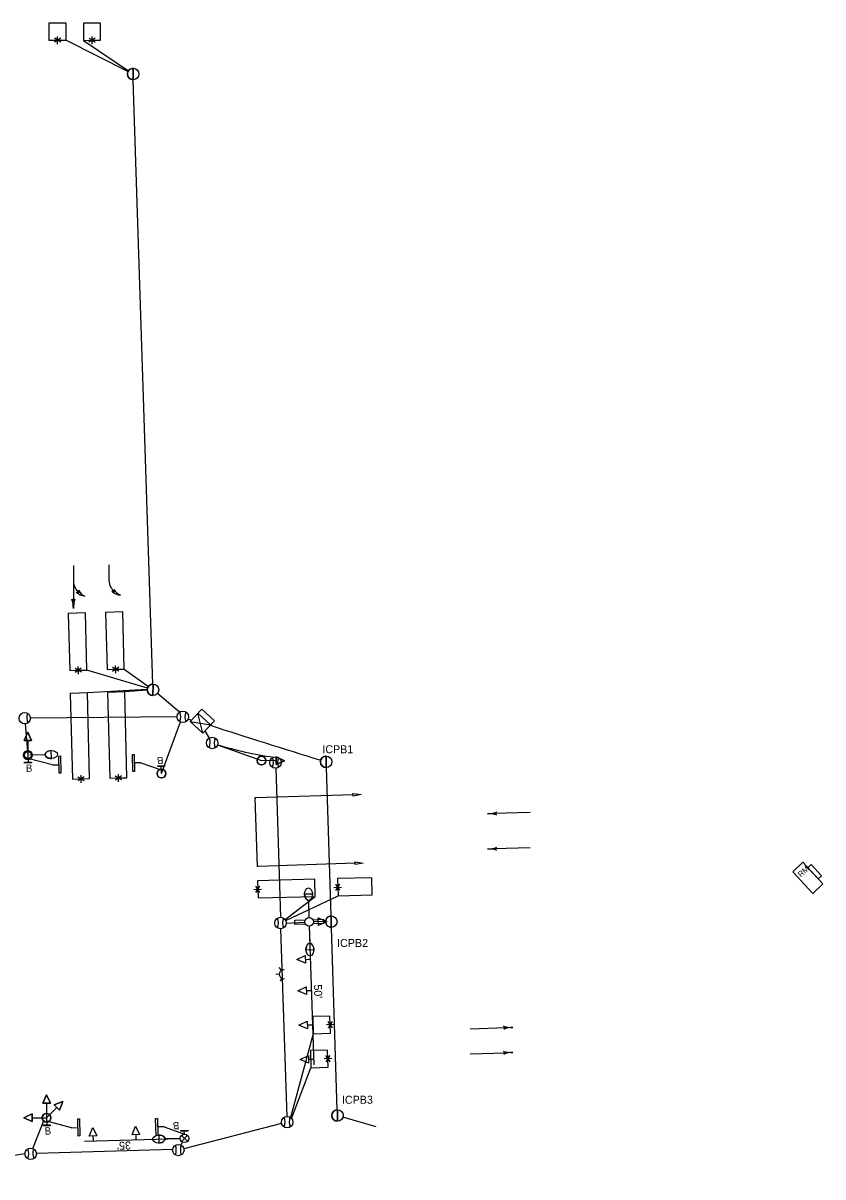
# Model space of a CAD drawing. Extents: x 596176 to 605330, y 332416 to 402398.
# Drawn here: x 604030.9 to 604310.8, y 339271.7 to 339675.2 of the extents above; entities that cross this region are included whole.
import ezdxf

# ---------------------------------------------------------------- set-up
doc = ezdxf.new("R2010")
doc.units = 0
for name, color, linetype in [('P_LTG', 7, 'Continuous'), ('P_SIG', 7, 'Continuous'), ('P_SIG_Bold', 7, 'Continuous'), ('P_SIG_Conduit', 7, 'Continuous'), ('P_SIG_IC', 7, 'Continuous'), ('P_SIG_Loops', 7, 'Continuous'), ('P_SIG_Text', 7, 'Continuous')]:
    doc.layers.add(name, color=color, linetype=linetype)

# ---------------------------------------------------------------- blocks, each defined once
blk = doc.blocks.new('LUMINAIRES')
at = {"layer": 'P_LTG'}
for p, q in [((4.3, 25.1), (-4.1, 25.1)), ((0, 2.3), (0, 18.4))]:
    blk.add_line(p, q, dxfattribs=at)
blk.add_circle((0, 0.1), 3.68, dxfattribs=at)
blk.add_ellipse((0.1, 25.1), major_axis=(0, 6.65), ratio=0.636439, dxfattribs=at)
blk.add_ellipse((0.1, 25.1), major_axis=(0, 6.65), ratio=0.636439, start_param=1.570796, end_param=4.712389, dxfattribs=at)
blk = doc.blocks.new('_U314')
at = {"layer": 'P_LTG'}
for p, q in [((4.3, 25.1), (-4.1, 25.1)), ((0, 2.3), (0, 18.4))]:
    blk.add_line(p, q, dxfattribs=at)
blk.add_ellipse((0.1, 25.1), major_axis=(0, 6.65), ratio=0.636439, dxfattribs=at)
blk.add_ellipse((0.1, 25.1), major_axis=(0, 6.65), ratio=0.636439, start_param=1.570796, end_param=4.712389, dxfattribs=at)
blk = doc.blocks.new('CONTROL CABINET')
at = {"layer": 'P_SIG'}
for p, q in [((-0.229, 0.305), (0.229, 0.305)), ((-0.229, -0.152), (-0.229, 0.305)), ((-0.229, 0.152), (0.229, 0.152)), ((-0.229, -0.152), (0.229, 0.152)), ((0.229, -0.152), (-0.229, 0.152)), ((0.229, 0.305), (0.229, -0.152)), ((0.229, -0.152), (-0.229, -0.152))]:
    blk.add_line(p, q, dxfattribs=at)
blk = doc.blocks.new('_U226')
at = {"layer": 'P_SIG'}
blk.add_line((0, 6.1), (0, -6.1), dxfattribs=at)
blk.add_lwpolyline([(0, -6.1), (0, 6.1)], dxfattribs=at)
blk.add_circle((0, 0), 6.1, dxfattribs=at)
for start, end in [(89.7008, 180), (180, 269.7008)]:
    blk.add_arc((0, 0), 6.1, start, end, dxfattribs=at)

msp = doc.modelspace()

# ---------------------------------------------------------------- linework, layer by layer
at = {"layer": 'P_LTG'}
for p, q in [((604132.2, 339370.57), (604129.43, 339370.51)), ((604130.98, 339362.34), (604130.85, 339368.41)), ((604131.06, 339359.34), (604131.23, 339353.34)), ((604129.9, 339351.11), (604132.67, 339351.19))]:
    msp.add_line(p, q, dxfattribs=at)
for centre, major_axis in [((604130.81, 339370.54), (-0.05, 2.18)), ((604131.28, 339351.15), (0.06, -2.18))]:
    msp.add_ellipse(centre, major_axis=major_axis, ratio=0.636439, dxfattribs=at)
for centre, major_axis in [((604130.81, 339370.54), (-0.05, 2.18)), ((604131.28, 339351.15), (0.06, -2.18))]:
    msp.add_ellipse(centre, major_axis=major_axis, ratio=0.636439, start_param=1.570796, end_param=4.712389, dxfattribs=at)
at = {"layer": 'P_SIG'}
for p, q in [((604069.47, 339659.4), (604069.45, 339655.4)), ((604048.53, 339485.47), (604048.53, 339479.88)), ((604048.53, 339485.47), (604048.53, 339472.9)), ((604060.95, 339485.78), (604060.95, 339480.19)), ((604049.54, 339476.18), (604050.48, 339475.93)), ((604050.3, 339476.83), (604050.48, 339475.93)), ((604061.95, 339476.49), (604062.89, 339476.25)), ((604062.71, 339477.14), (604062.89, 339476.25)), ((604076.38, 339444.01), (604076.36, 339440.01)), ((604089.39, 339430.9), (604093.47, 339435.3)), ((604092.11, 339433.83), (604096.51, 339429.75)), ((604093.79, 339426.82), (604092.11, 339433.83)), ((604093.47, 339435.3), (604097.87, 339431.21)), ((604093.79, 339426.82), (604089.39, 339430.9)), ((604089.39, 339430.9), (604096.51, 339429.75)), ((604097.87, 339431.21), (604093.79, 339426.82)), ((604032.58, 339424.27), (604032.57, 339419.21)), ((604041.2, 339415.78), (604032.53, 339418.02)), ((604032.57, 339419.21), (604032.65, 339416.71)), ((604041.2, 339415.78), (604043.6, 339415.83)), ((604072.09, 339416.52), (604069.69, 339416.47)), ((604072.09, 339416.52), (604079.22, 339413.99)), ((604119.42, 339417.24), (604114.36, 339417.25)), ((604079.31, 339412.71), (604079.23, 339415.21)), ((604208.36, 339399.14), (604195.79, 339398.75)), ((604208.36, 339386.78), (604195.79, 339386.39)), ((604134.26, 339360.94), (604132.49, 339360.89)), ((604129.67, 339347.74), (604131.44, 339347.8)), ((604121.38, 339343.95), (604120.48, 339344.93)), ((604120.56, 339342.52), (604119.33, 339342.5)), ((604121.41, 339341.16), (604120.83, 339340.08)), ((604130.02, 339336.8), (604131.79, 339336.85)), ((604130.4, 339324.8), (604132.17, 339324.86)), ((604187.29, 339323.49), (604199.85, 339323.88)), ((604187.29, 339314.71), (604199.85, 339315.1)), ((604130.77, 339312.81), (604132.54, 339312.86)), ((604039.16, 339297.42), (604039.15, 339292.36)), ((604042.7, 339295.96), (604039.15, 339292.36)), ((604034.09, 339292.37), (604039.15, 339292.36)), ((604039.15, 339292.36), (604039.23, 339289.86)), ((604047.85, 339288.86), (604039.19, 339291.11)), ((604047.85, 339288.86), (604050.25, 339288.92)), ((604070.36, 339286.41), (604070.41, 339284.64)), ((604080.23, 339289.18), (604077.83, 339289.13)), ((604080.23, 339289.18), (604087.36, 339286.64)), ((604087.36, 339286.64), (604087.33, 339287.65)), ((604055.36, 339285.97), (604055.42, 339284.2))]:
    msp.add_line(p, q, dxfattribs=at)
for points in [[(604069.45, 339655.4), (604069.47, 339659.4)], [(604048.03, 339473.7), (604048.53, 339472.9), (604049.03, 339473.7)], [(604076.36, 339440.01), (604076.38, 339444.01)], [(604032.58, 339427.23), (604033.9, 339424.27), (604031.26, 339424.27), (604032.58, 339427.23)], [(604033.9, 339424.27), (604032.58, 339427.23), (604031.26, 339424.27), (604033.9, 339424.27)], [(604122.38, 339417.24), (604119.42, 339415.92), (604119.42, 339418.56), (604122.38, 339417.24)], [(604119.42, 339415.92), (604122.38, 339417.24), (604119.42, 339418.56), (604119.42, 339415.92)], [(604196.58, 339399.28), (604195.79, 339398.75), (604196.61, 339398.28)], [(604196.58, 339386.92), (604195.79, 339386.39), (604196.61, 339385.92)], [(604199.07, 339323.36), (604199.85, 339323.88), (604199.04, 339324.36)], [(604199.07, 339314.58), (604199.85, 339315.1), (604199.04, 339315.58)], [(604039.16, 339300.38), (604040.48, 339297.42), (604037.84, 339297.42), (604039.16, 339300.38)], [(604040.48, 339297.42), (604039.16, 339300.38), (604037.84, 339297.42), (604040.48, 339297.42)], [(604044.78, 339298.07), (604043.64, 339295.04), (604041.76, 339296.88), (604044.78, 339298.07)], [(604043.64, 339295.04), (604044.78, 339298.07), (604041.76, 339296.88), (604043.64, 339295.04)], [(604031.13, 339292.37), (604034.09, 339293.69), (604034.09, 339291.05), (604031.13, 339292.37)], [(604034.09, 339293.69), (604031.13, 339292.37), (604034.09, 339291.05), (604034.09, 339293.69)]]:
    msp.add_lwpolyline(points, dxfattribs=at)
for points in [[(604031.45, 339416.68), (604033.85, 339416.75), (604033.86, 339416.43), (604031.46, 339416.35)], [(604043.53, 339412.87), (604043.39, 339418.87), (604043.99, 339418.88), (604044.13, 339412.88)], [(604069.76, 339419.43), (604069.89, 339413.43), (604069.29, 339413.42), (604069.16, 339419.42)], [(604080.43, 339415.24), (604078.03, 339415.17), (604078.02, 339415.49), (604080.42, 339415.57)], [(604310.76, 339374.11), (604303.72, 339381.69), (604300.18, 339378.41), (604307.23, 339370.83)], [(604306.7, 339380.88), (604305.53, 339379.79), (604309.12, 339375.93), (604310.29, 339377.02)], [(604137.21, 339361.03), (604134.29, 339359.62), (604134.22, 339362.26)], [(604126.71, 339347.65), (604129.62, 339349.06), (604129.71, 339346.43)], [(604127.06, 339336.7), (604129.97, 339338.11), (604130.06, 339335.48)], [(604127.44, 339324.71), (604130.36, 339326.12), (604130.44, 339323.49)], [(604127.81, 339312.71), (604130.73, 339314.12), (604130.81, 339311.49)], [(604050.18, 339285.96), (604050.05, 339291.95), (604050.65, 339291.97), (604050.78, 339285.97)], [(604077.9, 339292.08), (604078.03, 339286.09), (604077.43, 339286.07), (604077.3, 339292.07)], [(604038.03, 339289.82), (604040.43, 339289.9), (604040.44, 339289.57), (604038.04, 339289.5)], [(604055.27, 339288.92), (604056.68, 339286.01), (604054.05, 339285.93)], [(604070.26, 339289.37), (604071.67, 339286.45), (604069.04, 339286.37)], [(604088.53, 339287.69), (604086.13, 339287.61), (604086.12, 339287.94), (604088.52, 339288.01)]]:
    msp.add_lwpolyline(points, close=True, dxfattribs=at)
for centre, radius in [((604069.46, 339657.4), 2), ((604076.37, 339442.01), 2), ((604031.5, 339432.08), 2), ((604086.81, 339432.57), 2), ((604097.11, 339423.43), 2), ((604032.57, 339419.21), 1.52), ((604032.57, 339419.21), 1.52), ((604032.57, 339419.21), 1.52), ((604114.36, 339417.25), 1.52), ((604114.36, 339417.25), 1.52), ((604114.36, 339417.25), 1.52), ((604119.25, 339416.61), 2), ((604079.31, 339412.71), 1.52), ((604120.99, 339360.46), 2), ((604039.15, 339292.36), 1.52), ((604039.15, 339292.36), 1.52), ((604039.15, 339292.36), 1.52), ((604039.15, 339292.36), 1.52), ((604039.15, 339292.36), 1.52), ((604039.15, 339292.36), 1.52), ((604039.15, 339292.36), 1.52), ((604039.15, 339292.36), 1.52), ((604039.15, 339292.36), 1.52), ((604123.32, 339290.82), 2), ((604085.24, 339281.05), 2), ((604033.59, 339279.73), 2)]:
    msp.add_circle(centre, radius, dxfattribs=at)
for centre, radius, start, end in [((604069.46, 339657.4), 2, 89.7008, 180), ((604069.46, 339657.4), 2, 180, 269.7008), ((604066.73, 339480.59), 5.8, 183.9653, 228.5292), ((604054.32, 339480.28), 5.8, 183.9653, 228.5292), ((604053.53, 339480.75), 6.07, 228.8285, 260.6847), ((604054.75, 339479.41), 5.14, 210.0849, 244.7333), ((604065.95, 339481.06), 6.07, 228.8285, 260.6847), ((604067.16, 339479.72), 5.14, 210.0849, 244.7333), ((604038.04, 339470.5), 10.49, 360, 17.7623), ((604059.02, 339470.5), 10.49, 162.2377, 180), ((604076.37, 339442.01), 2, 89.7008, 180), ((604076.37, 339442.01), 2, 180, 269.7008), ((604036.57, 339432.13), 4.36, 157.5751, 203.4282), ((604081.74, 339432.61), 4.36, 336.6741, 22.5272), ((604091.88, 339432.61), 4.36, 157.5751, 203.4282), ((604092.04, 339423.47), 4.36, 336.6741, 22.5272), ((604102.18, 339423.48), 4.36, 157.5751, 203.4282), ((604032.57, 339419.21), 1.52, 90, 270), ((604032.57, 339419.21), 1.52, 270, 90), ((604114.36, 339417.25), 1.52, 0, 180), ((604114.36, 339417.25), 1.52, 180, 0), ((604114.18, 339416.65), 4.36, 336.6741, 22.5272), ((604124.32, 339416.66), 4.36, 157.5751, 203.4282), ((604079.31, 339412.71), 1.52, 0, 180), ((604079.31, 339412.71), 1.52, 180, 0), ((604193.07, 339409.16), 10.49, 271.7654, 289.5278), ((604193.72, 339388.19), 10.49, 74.0031, 91.7654), ((604193.07, 339396.81), 10.49, 271.7654, 289.5278), ((604193.72, 339375.84), 10.49, 74.0031, 91.7654), ((604115.92, 339360.5), 4.36, 336.6741, 22.5272), ((604126.06, 339360.51), 4.36, 157.5751, 203.4282), ((604122.14, 339342.56), 1.58, 83.3712, 278.8787), ((604201.93, 339334.44), 10.49, 254.0073, 271.7696), ((604202.58, 339313.47), 10.49, 91.7696, 109.5319), ((604201.93, 339325.66), 10.49, 254.0073, 271.7696), ((604202.58, 339304.69), 10.49, 91.7696, 109.5319), ((604039.15, 339292.36), 1.52, 0, 180), ((604039.15, 339292.36), 1.52, 45.5187, 225.5187), ((604039.15, 339292.36), 1.52, 90, 270), ((604039.15, 339292.36), 1.52, 180, 0), ((604039.15, 339292.36), 1.52, 225.5187, 45.5187), ((604039.15, 339292.36), 1.52, 270, 90), ((604118.25, 339290.85), 4.36, 336.6741, 22.5272), ((604128.39, 339290.86), 4.36, 157.5751, 203.4282), ((604080.17, 339281.09), 4.36, 336.6741, 22.5272), ((604090.31, 339281.1), 4.36, 157.5751, 203.4282), ((604028.52, 339279.77), 4.36, 336.6741, 22.5272), ((604038.66, 339279.78), 4.36, 157.5751, 203.4282)]:
    msp.add_arc(centre, radius, start, end, dxfattribs=at)
at = {"layer": 'P_SIG_Bold'}
for p, q in [((604131.05, 339359.34), (604132.61, 339310.86)), ((604052.41, 339284.11), (604085.9, 339285.1)), ((604086.31, 339286.17), (604088.49, 339284.12)), ((604088.43, 339286.24), (604086.37, 339284.05))]:
    msp.add_line(p, q, dxfattribs=at)
for points in [[(604129.73, 339360.05), (604126.03, 339359.93), (604125.98, 339361.43), (604129.68, 339361.55)], [(604132.28, 339361.63), (604135.98, 339361.75), (604136.02, 339360.25), (604132.32, 339360.13)]]:
    msp.add_lwpolyline(points, dxfattribs=at)
for centre in [(604131, 339360.84), (604087.4, 339285.14)]:
    msp.add_circle(centre, 1.5, dxfattribs=at)
at = {"layer": 'P_SIG_Conduit'}
for p, q in [((604123.26, 339292.82), (604121.13, 339358.47)), ((604086.17, 339282.82), (604086.7, 339283.82)), ((604031.59, 339279.68), (603979.32, 339271.66)), ((604083.24, 339281.19), (604035.59, 339279.8))]:
    msp.add_line(p, q, dxfattribs=at)
for points in [[(604076.31, 339444.01), (604069.4, 339655.4)], [(604085.68, 339434.22), (604077.91, 339440.73)], [(604084.81, 339432.55), (604033.5, 339432.1)], [(604088.69, 339431.88), (604089.89, 339431.44)], [(604031.67, 339430.09), (604032.57, 339419.21)], [(604079.31, 339412.71), (604085.94, 339430.77)], [(604094.56, 339427.65), (604096.08, 339425.14)], [(604098.99, 339422.76), (604114.36, 339417.25)], [(604119.33, 339414.62), (604121, 339362.46)], [(604122.99, 339360.45), (604129.5, 339360.76)], [(604137.13, 339361.04), (604132.5, 339360.89)], [(604034.33, 339281.59), (604038.33, 339291.62)], [(604121.39, 339290.32), (604087.19, 339281.49)]]:
    msp.add_lwpolyline(points, dxfattribs=at)
msp.add_arc((604137.47, 339549.05), 131.96, 253.0559, 261.7336, dxfattribs=at)
at = {"layer": 'P_SIG_IC'}
for p, q in [((604138.69, 339362.92), (604137.02, 339414.83)), ((604140.86, 339295.11), (604138.81, 339358.92)), ((604154.49, 339289.13), (604142.84, 339292.55))]:
    msp.add_line(p, q, dxfattribs=at)
msp.add_arc((604953.99, 342080.15), 2785.82, 252.07054, 252.90432, dxfattribs=at)
at = {"layer": 'P_SIG_Loops'}
for p, q in [((604044.08, 339669.95), (604041.91, 339668.51)), ((604044.1, 339668.49), (604041.92, 339669.9)), ((604043.01, 339667.84), (604043.01, 339670.52)), ((604056.15, 339669.92), (604053.98, 339668.49)), ((604056.16, 339668.47), (604053.99, 339669.87)), ((604055.08, 339667.81), (604055.07, 339670.49)), ((604042.99, 339669.21), (604045.99, 339669.22)), ((604045.99, 339669.21), (604067.68, 339658.31)), ((604052.06, 339669.18), (604067.81, 339658.53)), ((604055.06, 339669.19), (604058.06, 339669.19)), ((604051.35, 339448.16), (604049.14, 339449.52)), ((604051.3, 339449.62), (604049.17, 339448.13)), ((604050.28, 339447.48), (604050.21, 339450.16)), ((604050.23, 339448.85), (604053.23, 339448.93)), ((604074.46, 339442.58), (604053.23, 339448.93)), ((604064.42, 339448.5), (604062.21, 339449.85)), ((604064.37, 339449.95), (604062.23, 339448.46)), ((604063.35, 339447.82), (604063.28, 339450.49)), ((604063.29, 339449.19), (604066.29, 339449.27)), ((604066.29, 339449.27), (604074.75, 339443.18)), ((604074.38, 339442.15), (604053.43, 339440.94)), ((604074.38, 339441.86), (604066.5, 339441.26)), ((604052.33, 339410.18), (604050.12, 339411.53)), ((604052.28, 339411.63), (604050.15, 339410.14)), ((604051.26, 339409.5), (604051.19, 339412.17)), ((604065.4, 339410.5), (604063.19, 339411.85)), ((604065.35, 339411.96), (604063.21, 339410.47)), ((604064.33, 339409.82), (604064.26, 339412.5)), ((604051.21, 339410.87), (604054.21, 339410.95)), ((604064.27, 339411.19), (604067.27, 339411.27)), ((604112.01, 339404.25), (604112.78, 339380.26)), ((604111.67, 339372.22), (604114.35, 339372.28)), ((604113.8, 339371.19), (604112.32, 339373.33)), ((604112.35, 339371.15), (604113.7, 339373.35)), ((604113.04, 339372.27), (604113.12, 339369.27)), ((604139.66, 339372.94), (604142.34, 339373.01)), ((604141.79, 339371.92), (604140.31, 339374.05)), ((604140.34, 339371.87), (604141.69, 339374.08)), ((604122.58, 339361.68), (604133.1, 339369.79)), ((604122.8, 339361.32), (604141.11, 339369.99)), ((604138.33, 339324.9), (604138.23, 339327.9)), ((604139.7, 339324.96), (604137.02, 339324.87)), ((604137.56, 339325.97), (604139.06, 339323.84)), ((604139.01, 339326.02), (604137.67, 339323.81)), ((604132.42, 339321.71), (604124.51, 339292.43)), ((604137.54, 339313.01), (604137.45, 339316)), ((604138.91, 339313.07), (604136.24, 339312.98)), ((604136.77, 339314.08), (604138.27, 339311.95)), ((604138.23, 339314.13), (604136.89, 339311.92)), ((604124.86, 339292.1), (604131.64, 339309.82))]:
    msp.add_line(p, q, dxfattribs=at)
for points in [[(604045.99, 339669.22), (604045.98, 339675.22), (604039.98, 339675.21), (604039.99, 339669.21)], [(604058.06, 339669.19), (604058.05, 339675.19), (604052.05, 339675.18), (604052.06, 339669.18)], [(604053.23, 339448.93), (604052.71, 339468.93), (604046.71, 339468.77), (604047.23, 339448.78)], [(604066.29, 339449.27), (604065.78, 339469.26), (604059.78, 339469.1), (604060.29, 339449.11)], [(604054.21, 339410.95), (604053.43, 339440.94), (604047.44, 339440.78), (604048.21, 339410.79)], [(604067.27, 339411.27), (604066.5, 339441.26), (604060.5, 339441.11), (604061.27, 339411.12)], [(604146.33, 339405.81), (604149.15, 339405.44), (604146.36, 339404.88)], [(604147.1, 339381.83), (604149.92, 339381.45), (604147.13, 339380.89)], [(604113.12, 339369.27), (604133.11, 339369.79), (604132.96, 339375.78), (604112.96, 339375.27)], [(604141.11, 339369.99), (604153.1, 339370.3), (604152.95, 339376.3), (604140.95, 339375.99)], [(604138.23, 339327.9), (604132.24, 339327.71), (604132.42, 339321.71), (604138.42, 339321.9)], [(604137.45, 339316), (604131.45, 339315.82), (604131.64, 339309.82), (604137.64, 339310.01)]]:
    msp.add_lwpolyline(points, close=True, dxfattribs=at)
for points in [[(604112.37, 339404.25), (604112.01, 339404.25)], [(604146.35, 339405.35), (604112.37, 339404.25)], [(604113.14, 339380.26), (604112.78, 339380.26)], [(604147.12, 339381.36), (604113.14, 339380.26)]]:
    msp.add_lwpolyline(points, dxfattribs=at)

# ---------------------------------------------------------------- block references
at = {"layer": 'P_SIG'}
for name, p, xscale, yscale, rotation in [('CONTROL CABINET', (604092.95, 339430.32), 13.123333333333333, 13.123333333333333, -43.04627252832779), ('LUMINAIRES', (604032.58, 339419.22), 0.3280833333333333, 0.32808333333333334, -88.71467693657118), ('_U314', (604086.65, 339285.1), 0.3280833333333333, 0.32808333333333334, 91.56622295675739)]:
    msp.add_blockref(name, p, dxfattribs=dict(at, xscale=xscale, yscale=yscale, rotation=rotation))
at = {"layer": 'P_SIG_IC', "xscale": 0.32808333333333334, "yscale": 0.32808333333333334}
for p in [(604136.96, 339416.82), (604138.75, 339360.92), (604140.93, 339293.12)]:
    msp.add_blockref('_U226', p, dxfattribs=at)

# ---------------------------------------------------------------- texts
at = {"layer": 'P_SIG'}
for s, height, rotation, p in [('B', 2.52, 1.8373, (604031.94, 339413.32)), ('B', 2.52, 181.8373, (604079.96, 339418.58)), ('RM', 2, 42.8976, (604303.07, 339376.36)), ("50'", 2.8, 271.8373, (604132.66, 339338.95)), ('B', 2.52, 181.8373, (604085.52, 339290.88)), ('B', 2.52, 1.8373, (604038.53, 339286.44))]:
    msp.add_text(s, height=height, rotation=rotation, dxfattribs=at).set_placement(p)
at = {"layer": 'P_SIG_Bold'}
msp.add_text("35'", height=2.8, rotation=181.6965, dxfattribs=at).set_placement((604068.62, 339284.08))
at = {"layer": 'P_SIG_Text'}
for s, p in [('ICPB1', (604135.62, 339419.83)), ('ICPB2', (604140.79, 339352.08)), ('ICPB3', (604142.48, 339297.25))]:
    msp.add_text(s, height=2.8, dxfattribs=at).set_placement(p)

doc.saveas('drawing.dxf')
